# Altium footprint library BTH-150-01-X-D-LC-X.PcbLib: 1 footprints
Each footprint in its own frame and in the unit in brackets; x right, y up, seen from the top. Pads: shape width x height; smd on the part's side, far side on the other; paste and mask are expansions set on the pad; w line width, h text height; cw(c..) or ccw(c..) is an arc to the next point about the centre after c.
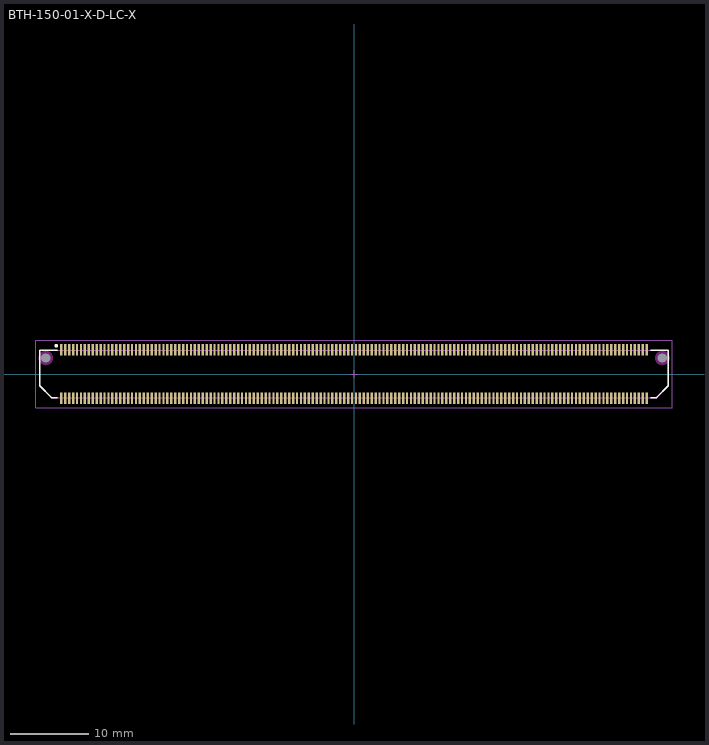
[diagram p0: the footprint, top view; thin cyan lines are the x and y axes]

## BTH-150-01-X-D-LC-X [mm] "0.50mm pitch, 300 pin, terminal strip; w/locking clips"
height 4.27
pads (302):
  rect 0.3x1.45 smd mask+0: 1(-37.25,3.086) 2(-37.25,-3.086) 3(-36.75,3.086) 4(-36.75,-3.086) 5(-36.25,3.086) 6(-36.25,-3.086) 7(-35.75,3.086) 8(-35.75,-3.086) 9(-35.25,3.086) 10(-35.25,-3.086) 11(-34.75,3.086) 12(-34.75,-3.086) 13(-34.25,3.086) 14(-34.25,-3.086) 15(-33.75,3.086) 16(-33.75,-3.086) 17(-33.25,3.086) 18(-33.25,-3.086) 19(-32.75,3.086) 20(-32.75,-3.086) 21(-32.25,3.086) 22(-32.25,-3.086) 23(-31.75,3.086) 24(-31.75,-3.086) 25(-31.25,3.086) 26(-31.25,-3.086) 27(-30.75,3.086) 28(-30.75,-3.086) 29(-30.25,3.086) 30(-30.25,-3.086) 31(-29.75,3.086) 32(-29.75,-3.086) 33(-29.25,3.086) 34(-29.25,-3.086) 35(-28.75,3.086) 36(-28.75,-3.086) 37(-28.25,3.086) 38(-28.25,-3.086) 39(-27.75,3.086) 40(-27.75,-3.086) 41(-27.25,3.086) 42(-27.25,-3.086) 43(-26.75,3.086) 44(-26.75,-3.086) 45(-26.25,3.086) 46(-26.25,-3.086) 47(-25.75,3.086) 48(-25.75,-3.086) 49(-25.25,3.086) 50(-25.25,-3.086) 51(-24.75,3.086) 52(-24.75,-3.086) 53(-24.25,3.086) 54(-24.25,-3.086) 55(-23.75,3.086) 56(-23.75,-3.086) 57(-23.25,3.086) 58(-23.25,-3.086) 59(-22.75,3.086) 60(-22.75,-3.086) 61(-22.25,3.086) 62(-22.25,-3.086) 63(-21.75,3.086) 64(-21.75,-3.086) 65(-21.25,3.086) 66(-21.25,-3.086) 67(-20.75,3.086) 68(-20.75,-3.086) 69(-20.25,3.086) 70(-20.25,-3.086) 71(-19.75,3.086) 72(-19.75,-3.086) 73(-19.25,3.086) 74(-19.25,-3.086) 75(-18.75,3.086) 76(-18.75,-3.086) 77(-18.25,3.086) 78(-18.25,-3.086) 79(-17.75,3.086) 80(-17.75,-3.086) 81(-17.25,3.086) 82(-17.25,-3.086) 83(-16.75,3.086) 84(-16.75,-3.086) 85(-16.25,3.086) 86(-16.25,-3.086) 87(-15.75,3.086) 88(-15.75,-3.086) 89(-15.25,3.086) 90(-15.25,-3.086) 91(-14.75,3.086) 92(-14.75,-3.086) 93(-14.25,3.086) 94(-14.25,-3.086) 95(-13.75,3.086) 96(-13.75,-3.086) 97(-13.25,3.086) 98(-13.25,-3.086) 99(-12.75,3.086) 100(-12.75,-3.086) 101(-12.25,3.086) 102(-12.25,-3.086) 103(-11.75,3.086) 104(-11.75,-3.086) 105(-11.25,3.086) 106(-11.25,-3.086) 107(-10.75,3.086) 108(-10.75,-3.086) 109(-10.25,3.086) 110(-10.25,-3.086) 111(-9.75,3.086) 112(-9.75,-3.086) 113(-9.25,3.086) 114(-9.25,-3.086) 115(-8.75,3.086) 116(-8.75,-3.086) 117(-8.25,3.086) 118(-8.25,-3.086) 119(-7.75,3.086) 120(-7.75,-3.086) 121(-7.25,3.086) 122(-7.25,-3.086) 123(-6.75,3.086) 124(-6.75,-3.086) 125(-6.25,3.086) 126(-6.25,-3.086) 127(-5.75,3.086) 128(-5.75,-3.086) 129(-5.25,3.086) 130(-5.25,-3.086) 131(-4.75,3.086) 132(-4.75,-3.086) 133(-4.25,3.086) 134(-4.25,-3.086) 135(-3.75,3.086) 136(-3.75,-3.086) 137(-3.25,3.086) 138(-3.25,-3.086) 139(-2.75,3.086) 140(-2.75,-3.086) 141(-2.25,3.086) 142(-2.25,-3.086) 143(-1.75,3.086) 144(-1.75,-3.086) 145(-1.25,3.086) 146(-1.25,-3.086) 147(-0.75,3.086) 148(-0.75,-3.086) 149(-0.25,3.086) 150(-0.25,-3.086) 151(0.25,3.086) 152(0.25,-3.086) 153(0.75,3.086) 154(0.75,-3.086) 155(1.25,3.086) 156(1.25,-3.086) 157(1.75,3.086) 158(1.75,-3.086) 159(2.25,3.086) 160(2.25,-3.086) 161(2.75,3.086) 162(2.75,-3.086) 163(3.25,3.086) 164(3.25,-3.086) 165(3.75,3.086) 166(3.75,-3.086) 167(4.25,3.086) 168(4.25,-3.086) 169(4.75,3.086) 170(4.75,-3.086) 171(5.25,3.086) 172(5.25,-3.086) 173(5.75,3.086) 174(5.75,-3.086) 175(6.25,3.086) 176(6.25,-3.086) 177(6.75,3.086) 178(6.75,-3.086) 179(7.25,3.086) 180(7.25,-3.086) 181(7.75,3.086) 182(7.75,-3.086) 183(8.25,3.086) 184(8.25,-3.086) 185(8.75,3.086) 186(8.75,-3.086) 187(9.25,3.086) 188(9.25,-3.086) 189(9.75,3.086) 190(9.75,-3.086) 191(10.25,3.086) 192(10.25,-3.086) 193(10.75,3.086) 194(10.75,-3.086) 195(11.25,3.086) 196(11.25,-3.086) 197(11.75,3.086) 198(11.75,-3.086) 199(12.25,3.086) 200(12.25,-3.086) 201(12.75,3.086) 202(12.75,-3.086) 203(13.25,3.086) 204(13.25,-3.086) 205(13.75,3.086) 206(13.75,-3.086) 207(14.25,3.086) 208(14.25,-3.086) 209(14.75,3.086) 210(14.75,-3.086) 211(15.25,3.086) 212(15.25,-3.086) 213(15.75,3.086) 214(15.75,-3.086) 215(16.25,3.086) 216(16.25,-3.086) 217(16.75,3.086) 218(16.75,-3.086) 219(17.25,3.086) 220(17.25,-3.086) 221(17.75,3.086) 222(17.75,-3.086) 223(18.25,3.086) 224(18.25,-3.086) 225(18.75,3.086) 226(18.75,-3.086) 227(19.25,3.086) 228(19.25,-3.086) 229(19.75,3.086) 230(19.75,-3.086) 231(20.25,3.086) 232(20.25,-3.086) 233(20.75,3.086) 234(20.75,-3.086) 235(21.25,3.086) 236(21.25,-3.086) 237(21.75,3.086) 238(21.75,-3.086) 239(22.25,3.086) 240(22.25,-3.086) 241(22.75,3.086) 242(22.75,-3.086) 243(23.25,3.086) 244(23.25,-3.086) 245(23.75,3.086) 246(23.75,-3.086) 247(24.25,3.086) 248(24.25,-3.086) 249(24.75,3.086) 250(24.75,-3.086) 251(25.25,3.086) 252(25.25,-3.086) 253(25.75,3.086) 254(25.75,-3.086) 255(26.25,3.086) 256(26.25,-3.086) 257(26.75,3.086) 258(26.75,-3.086) 259(27.25,3.086) 260(27.25,-3.086) 261(27.75,3.086) 262(27.75,-3.086) 263(28.25,3.086) 264(28.25,-3.086) 265(28.75,3.086) 266(28.75,-3.086) 267(29.25,3.086) 268(29.25,-3.086) 269(29.75,3.086) 270(29.75,-3.086) 271(30.25,3.086) 272(30.25,-3.086) 273(30.75,3.086) 274(30.75,-3.086) 275(31.25,3.086) 276(31.25,-3.086) 277(31.75,3.086) 278(31.75,-3.086) 279(32.25,3.086) 280(32.25,-3.086) 281(32.75,3.086) 282(32.75,-3.086) 283(33.25,3.086) 284(33.25,-3.086) 285(33.75,3.086) 286(33.75,-3.086) 287(34.25,3.086) 288(34.25,-3.086) 289(34.75,3.086) 290(34.75,-3.086) 291(35.25,3.086) 292(35.25,-3.086) 293(35.75,3.086) 294(35.75,-3.086) 295(36.25,3.086) 296(36.25,-3.086) 297(36.75,3.086) 298(36.75,-3.086) 299(37.25,3.086) 300(37.25,-3.086)
  round 0.5 hole 1.2 unplated mask+0: 301(-39.238,2.032) 302(39.252,2.032)
Top Overlay:
  circle w0.25: c-37.9,3.6 r0.125
  lines w0.2: -37.8,-3 -38.5,-3 -40,-1.5 -40,3 -37.8,3 ; 37.8,-3 38.5,-3 40,-1.5 40,3 37.8,3
Keep-Out Layer:
  pour cut-out: 40.16,2.032 40.129,2.267 40.038,2.486 39.894,2.674 39.706,2.818 39.487,2.909 39.252,2.94 39.017,2.909 38.798,2.818 38.61,2.674 38.466,2.486 38.375,2.267 38.344,2.032 38.375,1.797 38.466,1.578 38.61,1.39 38.798,1.246 39.017,1.155 39.252,1.124 39.487,1.155 39.706,1.246 39.894,1.39 40.038,1.578 40.129,1.797
  pour cut-out: -38.33,2.032 -38.361,2.267 -38.452,2.486 -38.596,2.674 -38.784,2.818 -39.003,2.909 -39.238,2.94 -39.473,2.909 -39.692,2.818 -39.88,2.674 -40.024,2.486 -40.115,2.267 -40.146,2.032 -40.115,1.797 -40.024,1.578 -39.88,1.39 -39.692,1.246 -39.473,1.155 -39.238,1.124 -39.003,1.155 -38.784,1.246 -38.596,1.39 -38.452,1.578 -38.361,1.797
Mechanical 12:
  lines w0.001: -40,-1.5 -40,3 40,3 40,-1.5 38.5,-3 -38.5,-3 -40,-1.5
Mechanical 13:
  lines w0.1: -40,-1.49 -40,3 40,3 40,-1.495 38.51,-3 -38.505,-3 -40,-1.49
  text ".Designator" at 0.254,0.254 h1.52
Mechanical 15:
  lines w0.05: -0.5,0 0.5,0 ; 0,-0.5 0,0.5 ; -40.5,-4.3 -40.5,4.3 40.5,4.3 40.5,-4.3 -40.5,-4.3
